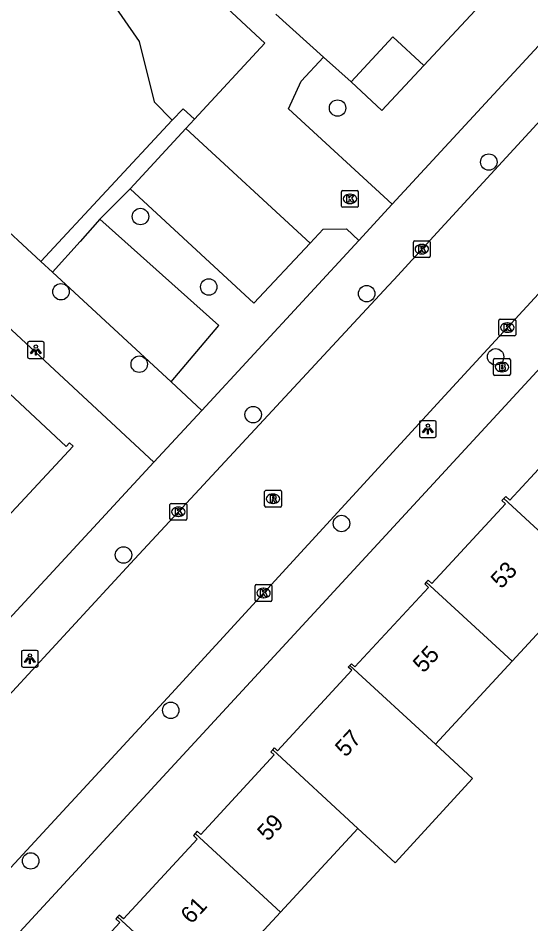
# Model space of a CAD drawing. Extents: x 159222 to 160346, y 381249 to 382166.
# Drawn here: x 159779.2 to 159809.7, y 381534.9 to 381588.8 of the extents above; entities that cross this region are included whole.
import ezdxf

# ---------------------------------------------------------------- set-up
doc = ezdxf.new("R2010")
doc.units = 0
for name, color, linetype in [('IMGEO_Boom', 7, 'Continuous'), ('IMGEO_Brandkraan', 7, 'Continuous'), ('IMGEO_Groenvoorziening', 7, 'Continuous'), ('IMGEO_Kolk', 7, 'Continuous'), ('IMGEO_Lichtpunt', 7, 'Continuous'), ('IMGEO_Pand', 7, 'Continuous'), ('IMGEO_Pand_nummerreeks', 7, 'Continuous'), ('IMGEO_Parkeervlak_open', 7, 'Continuous'), ('IMGEO_Rijbaan_lokaal_open', 7, 'Continuous'), ('IMGEO_Rioolput', 7, 'Continuous'), ('IMGEO_Voetpad_open', 7, 'Continuous')]:
    doc.layers.add(name, color=color, linetype=linetype)

msp = doc.modelspace()

# ---------------------------------------------------------------- linework, layer by layer
at = {"layer": 'IMGEO_Boom'}
for centre in [(159798.24, 381583.471), (159807.245, 381580.254), (159786.505, 381577.008), (159790.572, 381572.811), (159781.773, 381572.524), (159799.973, 381572.412), (159807.651, 381568.649), (159786.432, 381568.21), (159793.215, 381565.205), (159798.476, 381558.719), (159785.495, 381556.843), (159788.309, 381547.587), (159779.968, 381538.616)]:
    msp.add_circle(centre, 0.489, dxfattribs=at)
at = {"layer": 'IMGEO_Brandkraan'}
for p, q in [((159807.528, 381567.616), (159807.528, 381568.468)), ((159807.603, 381568.542), (159808.455, 381568.542)), ((159808.529, 381568.468), (159808.529, 381567.616)), ((159808.016, 381568.322), (159808.041, 381568.322)), ((159808.455, 381567.542), (159807.603, 381567.542)), ((159808.039, 381567.762), (159808.014, 381567.762))]:
    msp.add_line(p, q, dxfattribs=at)
for points in [[(159807.528, 381567.616), (159807.528, 381568.468)], [(159807.603, 381568.542), (159808.455, 381568.542)], [(159808.529, 381568.468), (159808.529, 381567.616)], [(159807.876, 381568.242), (159807.876, 381567.842), (159808.089, 381567.842)], [(159808.107, 381568.242), (159807.876, 381568.242)], [(159808.055, 381568.161), (159808.001, 381568.161), (159808.001, 381568.085)], [(159808.001, 381568.085), (159808.054, 381568.085)], [(159808.063, 381568.009), (159808.001, 381568.009), (159808.001, 381567.928)], [(159808.001, 381567.928), (159808.063, 381567.928)], [(159808.455, 381567.542), (159807.603, 381567.542)]]:
    msp.add_lwpolyline(points, dxfattribs=at)
for centre, radius, start, end in [((159807.605, 381568.466), 0.0765, 91.552, 178.448), ((159807.605, 381568.466), 0.0765, 91.552, 178.448), ((159808.453, 381568.466), 0.0765, 1.552, 88.448), ((159808.453, 381568.466), 0.0765, 1.552, 88.448), ((159808.056, 381568.123), 0.0379, 267.8285, 90.9355), ((159808.064, 381567.968), 0.0404, 269.8759, 90.5077), ((159808.095, 381568.093), 0.251, 268.6676, 293.5347), ((159808.111, 381568.097), 0.145, 59.4692, 91.5367), ((159808.136, 381568.144), 0.0922, 285.5137, 58.1501), ((159808.141, 381567.952), 0.105, 301.3115, 78.989), ((159807.605, 381567.618), 0.0765, 181.552, 268.448), ((159807.605, 381567.618), 0.0765, 181.552, 268.448), ((159808.453, 381567.618), 0.0765, 271.552, 358.448), ((159808.453, 381567.618), 0.0765, 271.552, 358.448)]:
    msp.add_arc(centre, radius, start, end, dxfattribs=at)
for centre, major_axis, ratio, start_param, end_param in [((159808.015, 381568.042), (-0.387, 0.002), 0.722429, 4.712389, 7.853982), ((159808.04, 381568.042), (-0.39, 0.002), 0.717154, 1.570796, 4.712389)]:
    msp.add_ellipse(centre, major_axis=major_axis, ratio=ratio, start_param=start_param, end_param=end_param, dxfattribs=at)
at = {"layer": 'IMGEO_Groenvoorziening'}
for points in [[(159774.092, 381589.012), (159775.732, 381590.085), (159779.873, 381594.699), (159783.341, 381591.926), (159786.426, 381587.433), (159787.316, 381583.835), (159788.398, 381582.74)], [(159803.375, 381586.01), (159807.261, 381590.19)], [(159797.402, 381586.508), (159799.047, 381585.03)], [(159788.326, 381567.158), (159791.173, 381570.52), (159784.082, 381576.847)]]:
    msp.add_lwpolyline(points, dxfattribs=at)
at = {"layer": 'IMGEO_Kolk'}
for p, q in [((159798.476, 381577.633), (159798.476, 381578.485)), ((159798.551, 381578.559), (159799.403, 381578.559)), ((159798.964, 381578.339), (159798.989, 381578.339)), ((159799.477, 381578.485), (159799.477, 381577.633)), ((159799.403, 381577.559), (159798.551, 381577.559)), ((159798.987, 381577.779), (159798.962, 381577.779)), ((159802.756, 381574.638), (159802.756, 381575.49)), ((159802.831, 381575.564), (159803.683, 381575.564)), ((159803.757, 381575.49), (159803.757, 381574.638)), ((159803.244, 381575.344), (159803.269, 381575.344)), ((159803.683, 381574.564), (159802.831, 381574.564)), ((159803.267, 381574.784), (159803.242, 381574.784)), ((159807.845, 381569.964), (159807.845, 381570.816)), ((159807.92, 381570.89), (159808.772, 381570.89)), ((159808.333, 381570.67), (159808.358, 381570.67)), ((159808.846, 381570.816), (159808.846, 381569.964)), ((159808.356, 381570.11), (159808.331, 381570.11)), ((159808.772, 381569.89), (159807.92, 381569.89)), ((159788.261, 381558.99), (159788.261, 381559.842)), ((159788.336, 381559.916), (159789.188, 381559.916)), ((159789.262, 381559.842), (159789.262, 381558.99)), ((159788.749, 381559.696), (159788.774, 381559.696)), ((159789.188, 381558.916), (159788.336, 381558.916)), ((159788.772, 381559.136), (159788.747, 381559.136)), ((159793.332, 381554.151), (159793.332, 381555.003)), ((159793.407, 381555.077), (159794.259, 381555.077)), ((159794.333, 381555.003), (159794.333, 381554.151)), ((159793.82, 381554.857), (159793.845, 381554.857)), ((159794.259, 381554.077), (159793.407, 381554.077)), ((159793.843, 381554.297), (159793.818, 381554.297))]:
    msp.add_line(p, q, dxfattribs=at)
for points in [[(159798.476, 381577.633), (159798.476, 381578.485)], [(159798.551, 381578.559), (159799.403, 381578.559)], [(159798.797, 381578.259), (159798.92, 381578.259), (159798.92, 381578.108), (159799.05, 381578.259), (159799.214, 381578.259), (159799.068, 381578.108), (159799.221, 381577.859), (159799.069, 381577.859), (159798.984, 381578.023), (159798.92, 381577.956), (159798.92, 381577.859), (159798.797, 381577.859), (159798.797, 381578.259)], [(159799.477, 381578.485), (159799.477, 381577.633)], [(159799.403, 381577.559), (159798.551, 381577.559)], [(159802.756, 381574.638), (159802.756, 381575.49)], [(159802.831, 381575.564), (159803.683, 381575.564)], [(159803.757, 381575.49), (159803.757, 381574.638)], [(159803.077, 381575.264), (159803.2, 381575.264), (159803.2, 381575.113), (159803.33, 381575.264), (159803.494, 381575.264), (159803.348, 381575.113), (159803.501, 381574.864), (159803.349, 381574.864), (159803.264, 381575.028), (159803.2, 381574.961), (159803.2, 381574.864), (159803.077, 381574.864), (159803.077, 381575.264)], [(159803.683, 381574.564), (159802.831, 381574.564)], [(159807.845, 381569.964), (159807.845, 381570.816)], [(159807.92, 381570.89), (159808.772, 381570.89)], [(159808.166, 381570.59), (159808.289, 381570.59), (159808.289, 381570.439), (159808.419, 381570.59), (159808.583, 381570.59), (159808.437, 381570.439), (159808.59, 381570.19), (159808.438, 381570.19), (159808.353, 381570.354), (159808.289, 381570.287), (159808.289, 381570.19), (159808.166, 381570.19), (159808.166, 381570.59)], [(159808.846, 381570.816), (159808.846, 381569.964)], [(159808.772, 381569.89), (159807.92, 381569.89)], [(159788.261, 381558.99), (159788.261, 381559.842)], [(159788.336, 381559.916), (159789.188, 381559.916)], [(159789.262, 381559.842), (159789.262, 381558.99)], [(159788.582, 381559.616), (159788.705, 381559.616), (159788.705, 381559.465), (159788.835, 381559.616), (159788.999, 381559.616), (159788.853, 381559.465), (159789.006, 381559.216), (159788.854, 381559.216), (159788.769, 381559.38), (159788.705, 381559.313), (159788.705, 381559.216), (159788.582, 381559.216), (159788.582, 381559.616)], [(159789.188, 381558.916), (159788.336, 381558.916)], [(159793.332, 381554.151), (159793.332, 381555.003)], [(159793.407, 381555.077), (159794.259, 381555.077)], [(159794.333, 381555.003), (159794.333, 381554.151)], [(159793.653, 381554.777), (159793.776, 381554.777), (159793.776, 381554.626), (159793.906, 381554.777), (159794.07, 381554.777), (159793.924, 381554.626), (159794.077, 381554.377), (159793.925, 381554.377), (159793.84, 381554.541), (159793.776, 381554.474), (159793.776, 381554.377), (159793.653, 381554.377), (159793.653, 381554.777)], [(159794.259, 381554.077), (159793.407, 381554.077)]]:
    msp.add_lwpolyline(points, dxfattribs=at)
for centre, start, end in [((159798.553, 381578.483), 91.552, 178.448), ((159798.553, 381578.483), 91.552, 178.448), ((159799.401, 381578.483), 1.552, 88.448), ((159799.401, 381578.483), 1.552, 88.448), ((159798.553, 381577.635), 181.552, 268.448), ((159798.553, 381577.635), 181.552, 268.448), ((159799.401, 381577.635), 271.552, 358.448), ((159799.401, 381577.635), 271.552, 358.448), ((159802.833, 381575.488), 91.552, 178.448), ((159802.833, 381575.488), 91.552, 178.448), ((159803.681, 381575.488), 1.552, 88.448), ((159803.681, 381575.488), 1.552, 88.448), ((159802.833, 381574.64), 181.552, 268.448), ((159802.833, 381574.64), 181.552, 268.448), ((159803.681, 381574.64), 271.552, 358.448), ((159803.681, 381574.64), 271.552, 358.448), ((159807.922, 381570.814), 91.552, 178.448), ((159807.922, 381570.814), 91.552, 178.448), ((159808.77, 381570.814), 1.552, 88.448), ((159808.77, 381570.814), 1.552, 88.448), ((159807.922, 381569.966), 181.552, 268.448), ((159807.922, 381569.966), 181.552, 268.448), ((159808.77, 381569.966), 271.552, 358.448), ((159808.77, 381569.966), 271.552, 358.448), ((159788.338, 381559.84), 91.552, 178.448), ((159788.338, 381559.84), 91.552, 178.448), ((159789.186, 381559.84), 1.552, 88.448), ((159789.186, 381559.84), 1.552, 88.448), ((159788.338, 381558.992), 181.552, 268.448), ((159788.338, 381558.992), 181.552, 268.448), ((159789.186, 381558.992), 271.552, 358.448), ((159789.186, 381558.992), 271.552, 358.448), ((159793.409, 381555.001), 91.552, 178.448), ((159793.409, 381555.001), 91.552, 178.448), ((159794.257, 381555.001), 1.552, 88.448), ((159794.257, 381555.001), 1.552, 88.448), ((159793.409, 381554.153), 181.552, 268.448), ((159793.409, 381554.153), 181.552, 268.448), ((159794.257, 381554.153), 271.552, 358.448), ((159794.257, 381554.153), 271.552, 358.448)]:
    msp.add_arc(centre, 0.0765, start, end, dxfattribs=at)
for centre, major_axis, ratio, start_param, end_param in [((159798.963, 381578.059), (-0.387, 0.002), 0.722429, 4.712389, 7.853982), ((159798.988, 381578.059), (-0.39, 0.002), 0.717154, 1.570796, 4.712389), ((159803.243, 381575.064), (-0.387, 0.002), 0.722429, 4.712389, 7.853982), ((159803.268, 381575.064), (-0.39, 0.002), 0.717154, 1.570796, 4.712389), ((159808.332, 381570.39), (-0.387, 0.002), 0.722429, 4.712389, 7.853982), ((159808.357, 381570.39), (-0.39, 0.002), 0.717154, 1.570796, 4.712389), ((159788.748, 381559.416), (-0.387, 0.002), 0.722429, 4.712389, 7.853982), ((159788.773, 381559.416), (-0.39, 0.002), 0.717154, 1.570796, 4.712389), ((159793.819, 381554.577), (-0.387, 0.002), 0.722429, 4.712389, 7.853982), ((159793.844, 381554.577), (-0.39, 0.002), 0.717154, 1.570796, 4.712389)]:
    msp.add_ellipse(centre, major_axis=major_axis, ratio=ratio, start_param=start_param, end_param=end_param, dxfattribs=at)
at = {"layer": 'IMGEO_Lichtpunt'}
for p, q in [((159780.679, 381569.553), (159779.871, 381569.553)), ((159780.679, 381569.553), (159779.871, 381569.553)), ((159779.777, 381569.458), (159779.777, 381568.651)), ((159779.777, 381569.458), (159779.777, 381568.651)), ((159780.773, 381568.651), (159780.773, 381569.458)), ((159780.773, 381568.651), (159780.773, 381569.458)), ((159779.871, 381568.557), (159780.679, 381568.557)), ((159779.871, 381568.557), (159780.679, 381568.557)), ((159803.117, 381564.75), (159803.117, 381563.943)), ((159803.117, 381564.75), (159803.117, 381563.943)), ((159804.019, 381564.845), (159803.211, 381564.845)), ((159804.019, 381564.845), (159803.211, 381564.845)), ((159804.113, 381563.943), (159804.113, 381564.75)), ((159804.113, 381563.943), (159804.113, 381564.75)), ((159803.211, 381563.849), (159804.019, 381563.849)), ((159803.211, 381563.849), (159804.019, 381563.849)), ((159780.323, 381551.158), (159779.515, 381551.158)), ((159780.323, 381551.158), (159779.515, 381551.158)), ((159779.421, 381551.063), (159779.421, 381550.256)), ((159779.421, 381551.063), (159779.421, 381550.256)), ((159780.417, 381550.256), (159780.417, 381551.063)), ((159780.417, 381550.256), (159780.417, 381551.063)), ((159779.515, 381550.162), (159780.323, 381550.162)), ((159779.515, 381550.162), (159780.323, 381550.162))]:
    msp.add_line(p, q, dxfattribs=at)
for points in [[(159780.151, 381569.122), (159780.19, 381569.094), (159780.002, 381568.832), (159779.964, 381568.859), (159780.151, 381569.122)], [(159780.253, 381569.074), (159780.3, 381569.074), (159780.3, 381568.752), (159780.253, 381568.752), (159780.253, 381569.074)], [(159780.363, 381569.094), (159780.401, 381569.121), (159780.588, 381568.859), (159780.549, 381568.831), (159780.363, 381569.094)], [(159803.491, 381564.414), (159803.53, 381564.386), (159803.342, 381564.124), (159803.304, 381564.151), (159803.491, 381564.414)], [(159803.593, 381564.366), (159803.64, 381564.366), (159803.64, 381564.044), (159803.593, 381564.044), (159803.593, 381564.366)], [(159803.703, 381564.386), (159803.741, 381564.413), (159803.928, 381564.151), (159803.889, 381564.123), (159803.703, 381564.386)], [(159779.795, 381550.727), (159779.834, 381550.699), (159779.646, 381550.437), (159779.608, 381550.464), (159779.795, 381550.727)], [(159779.897, 381550.679), (159779.944, 381550.679), (159779.944, 381550.357), (159779.897, 381550.357), (159779.897, 381550.679)], [(159780.007, 381550.699), (159780.045, 381550.726), (159780.232, 381550.464), (159780.193, 381550.436), (159780.007, 381550.699)]]:
    msp.add_lwpolyline(points, dxfattribs=at)
for centre in [(159780.276, 381569.256), (159803.616, 381564.548), (159779.92, 381550.861)]:
    msp.add_circle(centre, 0.0994, dxfattribs=at)
for centre, start, end in [((159779.871, 381569.458), 90, 180), ((159779.871, 381569.458), 90, 180), ((159780.679, 381569.458), 0, 90), ((159780.679, 381569.458), 0, 90), ((159779.871, 381568.651), 180, 270), ((159779.871, 381568.651), 180, 270), ((159780.679, 381568.651), 270, 0), ((159780.679, 381568.651), 270, 360), ((159803.211, 381564.75), 90, 180), ((159803.211, 381564.75), 90, 180), ((159804.019, 381564.75), 0, 90), ((159804.019, 381564.75), 0, 90), ((159803.211, 381563.943), 180, 270), ((159803.211, 381563.943), 180, 270), ((159804.019, 381563.943), 270, 0), ((159804.019, 381563.943), 270, 360), ((159779.515, 381551.063), 90, 180), ((159779.515, 381551.063), 90, 180), ((159780.323, 381551.063), 0, 90), ((159780.323, 381551.063), 0, 90), ((159779.515, 381550.256), 180, 270), ((159779.515, 381550.256), 180, 270), ((159780.323, 381550.256), 270, 0), ((159780.323, 381550.256), 270, 360)]:
    msp.add_arc(centre, 0.0946, start, end, dxfattribs=at)
at = {"layer": 'IMGEO_Pand'}
for points in [[(159799.047, 381585.03), (159801.541, 381587.714), (159803.375, 381586.01)], [(159799.047, 381585.03), (159800.881, 381583.327), (159803.375, 381586.01)], [(159777.779, 381567.32), (159782.083, 381563.307), (159782.29, 381563.529), (159782.502, 381563.331), (159777.523, 381557.991), (159777.286, 381558.212), (159777.536, 381558.48), (159773.879, 381561.889), (159773.257, 381562.469)], [(159812.767, 381565.221), (159812.658, 381565.103), (159812.896, 381564.884), (159808.498, 381560.116), (159808.258, 381560.337), (159808.14, 381560.208)], [(159803.524, 381555.218), (159803.642, 381555.345), (159803.858, 381555.146), (159808.231, 381559.887), (159808.022, 381560.08), (159808.14, 381560.208)], [(159808.14, 381560.208), (159813.239, 381555.505)], [(159813.239, 381555.505), (159808.629, 381550.509)], [(159803.524, 381555.218), (159803.43, 381555.116), (159803.652, 381554.911), (159799.278, 381550.169), (159799.065, 381550.365), (159798.973, 381550.265)], [(159808.629, 381550.509), (159803.524, 381555.218)], [(159794.378, 381545.228), (159794.486, 381545.345), (159794.666, 381545.179), (159799.088, 381549.974), (159798.881, 381550.165), (159798.973, 381550.265)], [(159798.973, 381550.265), (159804.068, 381545.564)], [(159804.068, 381545.564), (159808.629, 381550.509)], [(159794.378, 381545.228), (159794.27, 381545.111), (159794.466, 381544.93), (159790.092, 381540.188), (159789.886, 381540.378), (159789.772, 381540.254)], [(159799.446, 381540.553), (159794.378, 381545.228)], [(159804.068, 381545.564), (159806.283, 381543.52), (159801.661, 381538.509), (159799.446, 381540.553)], [(159794.849, 381535.57), (159799.446, 381540.553)], [(159789.772, 381540.254), (159789.656, 381540.128), (159789.887, 381539.915), (159785.496, 381535.155), (159785.241, 381535.391), (159785.136, 381535.277)], [(159789.772, 381540.254), (159794.849, 381535.57)], [(159790.238, 381530.571), (159794.849, 381535.57)], [(159785.136, 381535.277), (159785.032, 381535.165), (159785.275, 381534.941), (159780.93, 381530.231), (159780.686, 381530.456), (159780.572, 381530.332)], [(159785.136, 381535.277), (159790.238, 381530.571)]]:
    msp.add_lwpolyline(points, dxfattribs=at)
at = {"layer": 'IMGEO_Parkeervlak_open'}
msp.add_lwpolyline([(159785.885, 381578.651), (159793.25, 381571.843), (159796.603, 381575.417)], dxfattribs=at)
at = {"layer": 'IMGEO_Rijbaan_lokaal_open'}
for points in [[(159817.636, 381590.721), (159804.171, 381576.061), (159801.602, 381573.265), (159801.251, 381572.882), (159785.904, 381556.333), (159775.346, 381544.9), (159761.914, 381530.376), (159758.111, 381526.231), (159757.686, 381525.939), (159757.191, 381525.658), (159756.672, 381525.422), (159756.135, 381525.234), (159755.583, 381525.094), (159755.021, 381525.004)], [(159761.898, 381520.03), (159768.221, 381526.805), (159788.349, 381548.598), (159804.623, 381566.347), (159822.289, 381585.535), (159822.436, 381585.689), (159822.853, 381586.072)]]:
    msp.add_lwpolyline(points, dxfattribs=at)
at = {"layer": 'IMGEO_Rioolput'}
for p, q in [((159793.899, 381559.769), (159793.899, 381560.621)), ((159793.974, 381560.695), (159794.826, 381560.695)), ((159794.387, 381560.475), (159794.412, 381560.475)), ((159794.9, 381560.621), (159794.9, 381559.769)), ((159794.41, 381559.915), (159794.385, 381559.915)), ((159794.826, 381559.695), (159793.974, 381559.695))]:
    msp.add_line(p, q, dxfattribs=at)
for points in [[(159793.899, 381559.769), (159793.899, 381560.621)], [(159793.974, 381560.695), (159794.826, 381560.695)], [(159794.488, 381560.393), (159794.236, 381560.395), (159794.236, 381559.995)], [(159794.414, 381560.314), (159794.36, 381560.314), (159794.36, 381560.233)], [(159794.9, 381560.621), (159794.9, 381559.769)], [(159794.236, 381559.995), (159794.36, 381559.995), (159794.36, 381560.157), (159794.371, 381560.157)], [(159794.36, 381560.233), (159794.412, 381560.233)], [(159794.418, 381560.128), (159794.489, 381559.995), (159794.629, 381559.995), (159794.564, 381560.121)], [(159794.826, 381559.695), (159793.974, 381559.695)]]:
    msp.add_lwpolyline(points, dxfattribs=at)
for centre, radius, start, end in [((159793.976, 381560.619), 0.0765, 91.552, 178.448), ((159793.976, 381560.619), 0.0765, 91.552, 178.448), ((159794.42, 381560.218), 0.0964, 77.0061, 93.1865), ((159794.434, 381560.275), 0.0378, 276.6634, 79.6772), ((159794.487, 381560.283), 0.109, 350.3612, 89.416), ((159794.824, 381560.619), 0.0765, 1.552, 88.448), ((159794.824, 381560.619), 0.0765, 1.552, 88.448), ((159793.976, 381559.771), 0.0765, 181.552, 268.448), ((159793.976, 381559.771), 0.0765, 181.552, 268.448), ((159794.37, 381560.104), 0.0533, 26.0293, 88.6989), ((159794.396, 381560.422), 0.19, 274.7715, 282.9687), ((159794.485, 381560.283), 0.112, 277.5842, 350.9817), ((159794.469, 381560.068), 0.108, 29.5134, 73.7905), ((159794.824, 381559.771), 0.0765, 271.552, 358.448), ((159794.824, 381559.771), 0.0765, 271.552, 358.448)]:
    msp.add_arc(centre, radius, start, end, dxfattribs=at)
for centre, major_axis, ratio, start_param, end_param in [((159794.386, 381560.195), (-0.387, 0.002), 0.722429, 4.712389, 7.853982), ((159794.411, 381560.195), (-0.39, 0.002), 0.717154, 1.570796, 4.712389)]:
    msp.add_ellipse(centre, major_axis=major_axis, ratio=ratio, start_param=start_param, end_param=end_param, dxfattribs=at)
at = {"layer": 'IMGEO_Voetpad_open'}
for points in [[(159743.027, 381603.569), (159787.302, 381562.373)], [(159782.155, 381598.273), (159793.91, 381587.329), (159789.727, 381582.805)], [(159815.991, 381593.468), (159801.486, 381577.736)], [(159797.402, 381586.508), (159794.564, 381589.058)], [(159801.486, 381577.736), (159795.325, 381583.417), (159796.068, 381585.081), (159797.402, 381586.508)], [(159764.137, 381517.952), (159824.319, 381583.193)], [(159788.398, 381582.74), (159789.038, 381583.428), (159789.727, 381582.805)], [(159780.572, 381574.328), (159771.559, 381582.662)], [(159780.572, 381574.328), (159788.398, 381582.74)], [(159789.727, 381582.805), (159789.214, 381582.25)], [(159785.885, 381578.651), (159789.214, 381582.25)], [(159789.214, 381582.25), (159796.603, 381575.417)], [(159784.082, 381576.847), (159785.885, 381578.651)], [(159799.507, 381575.589), (159801.486, 381577.736)], [(159784.082, 381576.847), (159782.91, 381575.517), (159781.262, 381573.69)], [(159796.603, 381575.417), (159797.383, 381576.248), (159798.773, 381576.267), (159799.507, 381575.589)], [(159799.507, 381575.589), (159790.166, 381565.457)], [(159781.262, 381573.69), (159780.572, 381574.328)], [(159788.326, 381567.158), (159781.262, 381573.69)], [(159790.166, 381565.457), (159788.326, 381567.158)], [(159787.302, 381562.373), (159790.166, 381565.457)], [(159774.33, 381548.327), (159787.302, 381562.373)]]:
    msp.add_lwpolyline(points, dxfattribs=at)

# ---------------------------------------------------------------- texts
at = {"layer": 'IMGEO_Pand_nummerreeks'}
for s, p in [('53', (159807.991, 381554.78)), ('55', (159803.357, 381549.765)), ('57', (159798.723, 381544.751)), ('59', (159794.089, 381539.737)), ('61', (159789.531, 381534.805))]:
    msp.add_text(s, height=1, rotation=47.2594, dxfattribs=at).set_placement(p)

doc.saveas('drawing.dxf')
